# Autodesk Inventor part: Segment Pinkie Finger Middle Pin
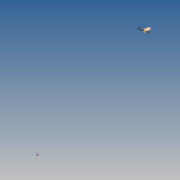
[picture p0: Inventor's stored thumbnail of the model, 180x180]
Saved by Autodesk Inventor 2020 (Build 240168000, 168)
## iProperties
Created: 2019-10
Part Number: Segment Pinkie Finger Middle Pin
Material: GFRP
Document SubType Name: Modeling
Designer: yello
Density: 1.75 g/cm^3
Appearance: Default
Author: yello
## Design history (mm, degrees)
feature "Paliczek MA"
sketch "Sketch1"
  geometry: C1 r 2 at (0, 0); 1 further point
  constraints: 1 centre point
  dimensions: "d0" = 4 dimension on point (105.522, -1045.143) C1.centre C1; "d0" = 4 diameter of C1
body "Solid1"
